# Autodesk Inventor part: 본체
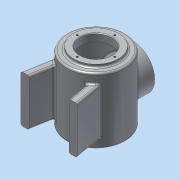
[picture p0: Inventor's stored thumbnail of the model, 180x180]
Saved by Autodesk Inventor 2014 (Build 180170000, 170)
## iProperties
Created: 2015-01
Part Number: 본체
Material: 알루미늄 6061
Document SubType Name: Modeling
Designer: user
Density: 2.71 g/cm^3
Appearance: 알루미늄 - 평지
Mass: 1021.18 g
Surface Area: 1060.35 cm^2
Volume: 376.818 cm^3
Author: user
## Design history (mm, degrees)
sketch "스케치1"
  geometry: C1 r 50 at (0, 0); 1 further point
  constraints: 1 centre point, 1 coincident
  dimensions: "d0" = 100 diameter of C1
extrude "돌출1" new body sketch "스케치1" stored distance "d1" = 112; taper "d2" = 0 deg
sketch "스케치2"
  geometry: C1 r 50 at (0, 0) reference; C2 r 38 at (0, 0)
  constraints: 1 centre point, 1 coincident
  dimensions: "d3" = 76 diameter of C2
extrude "돌출2" join sketch "스케치2" distance "d4" = 5; taper "d5" = 0 deg
sketch "스케치3"
  geometry: C1 r 50 at (0, 0) reference; C2 r 38 at (0, 0)
  constraints: 1 centre point, 1 coincident
  dimensions: "d6" = 76 diameter of C2
extrude "돌출3" join sketch "스케치3" distance "d7" = 5; taper "d8" = 0 deg
node "작업 평면2"
  node "작업 평면1"
sketch "스케치4"
  geometry: C1 r 38 at (0, 0); 1 further point
  constraints: 1 centre point, 1 coincident
  dimensions: "d10" = 76 diameter of C1
extrude "돌출4" join sketch "스케치4" stored distance "d11" = 5; taper "d12" = 0 deg
sketch "스케치5"
  geometry: L1 (-38.537, -26.331)-(-48, -80); L2 (-48, -80)-(-34, -80); L3 (-34, -80)-(-26.65, -38.317); L4 (38.537, -26.331)-(48, -80); L5 (48, -80)-(34, -80); L6 (34, -80)-(26.65, -38.317); L7 (-34, -80)-(67.419, -80); C1 r 50 at (0, 0) reference; A1 r 46.673 centre (0, 0) between (-38.537, -26.331) and (-26.65, -38.317); A2 r 46.673 centre (0, 0) between (26.65, -38.317) and (38.537, -26.331); 1 further point
  constraints: 14 end point, 4 point on circle, 3 equal length, 2 centre point, 2 horizontal, 2 parallel, 1 collinear, 1 horizontal alignment
  dimensions: "d13" = 80 vertical distance of L4.end point (0, 0); "d14" = 80 deg angle of L7 L6; "d15" = 14 distance of L4.end L5.end; "d16" = 96 distance of L4.end L1.end; "d17" = 48 horizontal distance of L4.end point (0, 0); "d19" = 46.67342 radius of A1
extrude "돌출5" join sketch "스케치5" stored distance "d20" = 80; taper "d21" = 0 deg
sketch "스케치6"
  geometry: C1 r 38 at (0, 0) reference; 1 further point
  constraints: 1 coincident
hole "구멍1" sketch "스케치6" at (0, 0) diameter "d22" = 54; stored, may be unused: countersink angle "d26" = 90 deg, drill point angle "d28" = 0 deg; dims "d23" = 6, "d24" = 4, "d25" = 2, "d27" = 13
sketch "스케치7"
  geometry: C1 r 27 at (0, 0) reference; 1 further point
  constraints: 1 coincident
hole "구멍2" sketch "스케치7" at (0, 0) diameter "d29" = 90; stored, may be unused: countersink angle "d33" = 90 deg, drill point angle "d35" = 0 deg; dims "d30" = 6, "d31" = 4, "d32" = 2, "d34" = 97
sketch "스케치8"
  geometry: C1 r 38 at (0, 0) reference; 1 further point
  constraints: 1 coincident
hole "구멍3" sketch "스케치8" at (0, 0) diameter "d36" = 54; stored, may be unused: countersink angle "d40" = 90 deg, drill point angle "d42" = 0 deg; dims "d37" = 6, "d38" = 4, "d39" = 2, "d41" = 12
sketch "스케치9"
  geometry: C1 r 38 at (0, 0) reference; 1 further point
  constraints: 1 coincident
hole "구멍4" sketch "스케치9" at (0, 0) diameter "d43" = 54; stored, may be unused: countersink angle "d47" = 90 deg, drill point angle "d49" = 0 deg; dims "d44" = 6, "d45" = 4, "d46" = 2, "d48" = 12
sketch "스케치10" dims "d50" = 64
  geometry: C1 r 27 at (0, 0) reference; C2 r 38 at (0, 0) reference; 2 further points
  constraints: 2 vertical alignment, 1 coincident, 2 other
hole "구멍5" sketch "스케치10" at (0, 32) diameter "d51" = 3.242; stored, may be unused: countersink angle "d55" = 90 deg, drill point angle "d57" = 118 deg; dims "d52" = 8, "d53" = 4, "d54" = 2, "d56" = 10
sketch "스케치11" dims "d61" = 64
  geometry: C1 r 27 at (0, 0) reference; C2 r 38 at (0, 0) reference; 2 further points
  constraints: 2 vertical alignment, 1 coincident, 2 other
hole "구멍6" sketch "스케치11" at (0, 32) diameter "d62" = 3.242; stored, may be unused: countersink angle "d66" = 90 deg, drill point angle "d68" = 118 deg; dims "d63" = 8, "d64" = 4, "d65" = 2, "d67" = 10
chamfer "모따기1" distance "d72" = 1; stored, may be unused: second distance "d73" = 2, angle "d74" = 45 deg
chamfer "모따기2" distance "d75" = 1; stored, may be unused: second distance "d76" = 2, angle "d77" = 45 deg
chamfer "모따기3" distance "d78" = 1; stored, may be unused: second distance "d79" = 2, angle "d80" = 45 deg
fillet "모깎기1" dims "d81" = 3
fillet "모깎기2" dims "d82" = 3
node "작업 평면4"
  node "작업 평면3"
sketch "스케치12"
  geometry: L1 (-6, -26)-(6, -26); L2 (6, -26)-(6, 28); L3 (6, 28)-(-6, 28); L4 (-6, 28)-(-6, -26); L5 (-6, 1)-(6, 1); L6 (38, 61)-(-38, 61) reference; L7 (-50, -53)-(50, -53) reference; 3 further points
  constraints: 10 end point, 4 midpoint, 2 parallel, 1 horizontal, 1 perpendicular, 1 vertical alignment
  dimensions: "d84" = 54 distance of L3.end L1.start; "d85" = 12 distance of L1.start L1.end; "d86" = 60 distance between parallel lines of L6 L5
extrude "돌출6" join sketch "스케치12" stored distance "d87" = 10; taper "d88" = 0 deg
sketch "스케치13"
  geometry: L1 (-26, 6)-(-26, -6) reference; L2 (28, 6)-(-26, 6) reference; 4 further points
  constraints: 2 midpoint, 1 horizontal alignment, 1 vertical alignment, 1 other
feature "엠보싱1" sketch "스케치13" dims "d11" = 5, "d12" = 0, "d89" = 0.5, "d90" = 0
fillet "모깎기3" dims "d91" = 3
node "솔리드1"
pattern_circular "원형 패턴1" dims angle "d59" = 360 deg
mirror "대칭1"
pattern_circular "원형 패턴2" dims angle "d70" = 360 deg
other parameters: "d9" = 12, "d83" = 2
